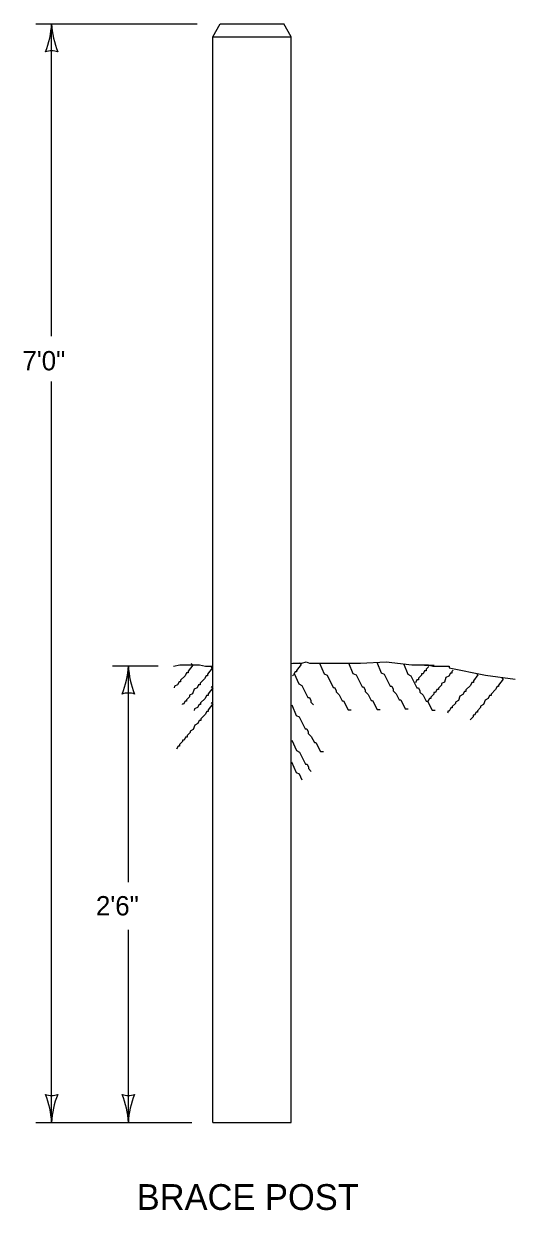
# Model space of a CAD drawing. Extents: x 49991 to 50288, y 49919 to 50011.
# Drawn here: x 50145.21 to 50148.35, y 49937.35 to 49944.96 of the extents above; entities that cross this region are included whole.
import ezdxf

# ---------------------------------------------------------------- set-up
doc = ezdxf.new("R2010")
doc.units = 0
for name, color, linetype in [('Level 1', 7, 'Continuous'), ('Level 2', 7, 'Continuous'), ('Level 5', 7, 'Continuous'), ('Level 7', 7, 'Continuous')]:
    doc.layers.add(name, color=color, linetype=linetype)

msp = doc.modelspace()

# ---------------------------------------------------------------- linework, layer by layer
at = {"layer": 'Level 1'}
for centre, radius, start, end in [((50144.8583, 49944.9773), 0.5262, 337.45601, 357.63952), ((50145.9349, 49944.9828), 0.5515, 182.82731, 202.07716), ((50145.3841, 49944.6521), 0.1296, 72.13882, 107.86118), ((50145.35, 49940.8626), 0.5262, 337.45601, 357.63952), ((50146.4265, 49940.8682), 0.5515, 182.82731, 202.07716), ((50145.8757, 49940.5375), 0.1296, 72.13882, 107.86118), ((50145.3841, 49938.2188), 0.1296, 252.13882, 287.86118), ((50144.8333, 49937.8882), 0.5515, 2.82731, 22.07716), ((50145.9099, 49937.8937), 0.5262, 157.45601, 177.63952), ((50145.8757, 49938.2188), 0.1296, 252.13882, 287.86118), ((50145.3249, 49937.8882), 0.5515, 2.82731, 22.07716), ((50146.4015, 49937.8937), 0.5262, 157.45601, 177.63952)]:
    msp.add_arc(centre, radius, start, end, dxfattribs=at)
at = {"layer": 'Level 5'}
msp.add_line((50147.7722, 49940.8452), (50147.833, 49940.8452), dxfattribs=at)
for points in [[(50146.1639, 49940.8401), (50146.2054, 49940.8483), (50146.3308, 49940.8483), (50146.3691, 49940.8387), (50146.417, 49940.8387)], [(50146.2777, 49940.8556), (50146.2874, 49940.8461), (50146.2586, 49940.8075), (50146.2586, 49940.7977), (50146.2488, 49940.7977), (50146.2393, 49940.7784), (50146.2102, 49940.7496), (50146.2102, 49940.74), (50146.2007, 49940.74), (50146.1909, 49940.7207), (50146.1718, 49940.711), (50146.1681, 49940.7002)], [(50146.4027, 49940.8362), (50146.4124, 49940.8266), (50146.3834, 49940.788), (50146.3834, 49940.7784), (50146.3738, 49940.7784), (50146.3641, 49940.7591), (50146.3352, 49940.7304), (50146.3352, 49940.7205), (50146.3255, 49940.7205), (50146.3159, 49940.7014), (50146.2968, 49940.6917), (50146.2869, 49940.6628), (50146.2677, 49940.6531), (50146.2677, 49940.6433), (50146.2484, 49940.624), (50146.2484, 49940.6146), (50146.2389, 49940.6146), (50146.229, 49940.5952), (50146.2195, 49940.5952), (50146.2195, 49940.593)], [(50146.9193, 49940.856), (50146.9283, 49940.858), (50146.9862, 49940.858), (50147.015, 49940.8675), (50147.0345, 49940.858), (50147.3331, 49940.858), (50147.3621, 49940.858), (50147.5262, 49940.8675), (50147.6898, 49940.8483), (50147.7959, 49940.8483), (50147.8246, 49940.8387), (50147.8922, 49940.8387), (50147.9306, 49940.8387), (50147.9306, 49940.829), (50148.1622, 49940.7808), (50148.3528, 49940.7563)], [(50146.9718, 49940.8604), (50146.9813, 49940.8506), (50146.9525, 49940.8122), (50146.9525, 49940.8026), (50146.9427, 49940.8026), (50146.9332, 49940.7833), (50146.9264, 49940.7765)], [(50147.0995, 49940.858), (50147.1283, 49940.7904), (50147.1476, 49940.7808), (50147.1861, 49940.7036), (50147.196, 49940.7036), (50147.2054, 49940.6843), (50147.2054, 49940.6748), (50147.2247, 49940.6555), (50147.244, 49940.6169), (50147.2537, 49940.6169), (50147.2826, 49940.5591), (50147.3019, 49940.5591)], [(50147.2849, 49940.8604), (50147.3138, 49940.7929), (50147.3332, 49940.7833), (50147.3717, 49940.7061), (50147.3814, 49940.7061), (50147.391, 49940.6868), (50147.391, 49940.6773), (50147.4103, 49940.658), (50147.4296, 49940.6194), (50147.4391, 49940.6194), (50147.4682, 49940.5616), (50147.4876, 49940.5616)], [(50147.4658, 49940.865), (50147.4946, 49940.7977), (50147.5139, 49940.788), (50147.5525, 49940.711), (50147.5621, 49940.711), (50147.5717, 49940.6917), (50147.5717, 49940.6822), (50147.5911, 49940.6627), (50147.6103, 49940.6241), (50147.6202, 49940.6241), (50147.6489, 49940.5664), (50147.6682, 49940.5664)], [(50147.6368, 49940.8556), (50147.6657, 49940.788), (50147.6851, 49940.7784), (50147.7236, 49940.7013), (50147.7331, 49940.7013), (50147.7429, 49940.6822), (50147.7429, 49940.6723), (50147.7623, 49940.653), (50147.7816, 49940.6145), (50147.791, 49940.6145), (50147.82, 49940.5566), (50147.8393, 49940.5566)], [(50147.7989, 49940.8368), (50147.7816, 49940.8193), (50147.7816, 49940.8097), (50147.7717, 49940.8097), (50147.7623, 49940.7906), (50147.7525, 49940.7906), (50147.7525, 49940.7808), (50147.733, 49940.7617), (50147.733, 49940.752), (50147.7236, 49940.752), (50147.714, 49940.7327)], [(50147.9556, 49940.813), (50147.9477, 49940.805), (50147.9477, 49940.7954), (50147.938, 49940.7954), (50147.9284, 49940.7763), (50147.9093, 49940.7664), (50147.8994, 49940.7375), (50147.8801, 49940.7279), (50147.8801, 49940.7182), (50147.8608, 49940.6989), (50147.8608, 49940.6893), (50147.8513, 49940.6893), (50147.8415, 49940.6702), (50147.832, 49940.6702), (50147.832, 49940.6605), (50147.8127, 49940.6412), (50147.8127, 49940.6316), (50147.8029, 49940.6316), (50147.7934, 49940.6121)], [(50146.9382, 49940.7927), (50146.967, 49940.7254), (50146.9862, 49940.7157), (50147.0248, 49940.6387), (50147.0345, 49940.6387), (50147.0441, 49940.6194), (50147.0441, 49940.6098), (50147.0619, 49940.592)], [(50148.1043, 49940.7929), (50148.114, 49940.7833), (50148.085, 49940.7447), (50148.085, 49940.7352), (50148.0754, 49940.7352), (50148.0657, 49940.7157), (50148.037, 49940.6868), (50148.037, 49940.6773), (50148.0271, 49940.6773), (50148.0176, 49940.658), (50147.9983, 49940.6482), (50147.9885, 49940.6195), (50147.9692, 49940.6098), (50147.9692, 49940.6002), (50147.9499, 49940.5809), (50147.9499, 49940.5714), (50147.9404, 49940.5714), (50147.9306, 49940.5521), (50147.9212, 49940.5521), (50147.9212, 49940.5423), (50147.9182, 49940.5393)], [(50148.2657, 49940.7664), (50148.2755, 49940.7566), (50148.2464, 49940.7182), (50148.2464, 49940.7086), (50148.2369, 49940.7086), (50148.2271, 49940.6893), (50148.1983, 49940.6605), (50148.1983, 49940.6507), (50148.1887, 49940.6507), (50148.179, 49940.6316), (50148.1597, 49940.622), (50148.1499, 49940.5928), (50148.1308, 49940.5833), (50148.1308, 49940.5737), (50148.1117, 49940.5541), (50148.1117, 49940.5447), (50148.1019, 49940.5447), (50148.0922, 49940.5254), (50148.0826, 49940.5254), (50148.0826, 49940.5157), (50148.0632, 49940.4964)], [(50146.4059, 49940.7101), (50146.4156, 49940.7006), (50146.3868, 49940.6619), (50146.3868, 49940.6521), (50146.377, 49940.6521), (50146.3675, 49940.6328), (50146.3384, 49940.604), (50146.3384, 49940.5944), (50146.3289, 49940.5944), (50146.3191, 49940.5751), (50146.3, 49940.5655), (50146.2964, 49940.5546)], [(50146.4063, 49940.6069), (50146.4159, 49940.5974), (50146.3869, 49940.5588), (50146.3869, 49940.549), (50146.3775, 49940.549), (50146.3677, 49940.5299), (50146.3389, 49940.501), (50146.3389, 49940.4913), (50146.3293, 49940.4913), (50146.3196, 49940.472), (50146.3003, 49940.4624), (50146.2905, 49940.4334), (50146.2712, 49940.4238), (50146.2712, 49940.4141), (50146.2519, 49940.3948), (50146.2519, 49940.3852), (50146.2424, 49940.3852), (50146.2329, 49940.3659), (50146.223, 49940.3659), (50146.223, 49940.3562), (50146.2037, 49940.337), (50146.2037, 49940.3272), (50146.1941, 49940.3272), (50146.1844, 49940.3081)], [(50146.9219, 49940.5916), (50146.9507, 49940.5241), (50146.97, 49940.5145), (50147.0085, 49940.4372), (50147.0184, 49940.4372), (50147.0278, 49940.4179), (50147.0278, 49940.4084), (50147.0471, 49940.3891), (50147.0665, 49940.3505), (50147.0762, 49940.3505), (50147.1051, 49940.2927), (50147.1244, 49940.2927)], [(50146.9234, 49940.366), (50146.9522, 49940.2987), (50146.9714, 49940.289), (50147.01, 49940.212), (50147.0197, 49940.212), (50147.0293, 49940.1927), (50147.0293, 49940.1831), (50147.0471, 49940.1653)], [(50146.9206, 49940.2257), (50146.9496, 49940.1582), (50146.9689, 49940.1487), (50146.9874, 49940.1114)]]:
    msp.add_lwpolyline(points, dxfattribs=at)
at = {"layer": 'Level 7'}
for p, q in [((50145.2835, 49944.9556), (50146.3171, 49944.9556)), ((50145.3841, 49942.9534), (50145.3841, 49944.9556)), ((50146.4158, 49944.8721), (50146.464, 49944.9556)), ((50146.464, 49944.9556), (50146.8705, 49944.9556)), ((50146.9187, 49944.8721), (50146.8705, 49944.9556)), ((50146.4158, 49944.8721), (50146.9187, 49944.8721)), ((50146.4158, 49937.9154), (50146.4158, 49944.8721)), ((50146.9187, 49943.6984), (50146.9187, 49944.8721)), ((50146.9187, 49937.9154), (50146.9187, 49943.6984)), ((50145.3841, 49937.9154), (50145.3841, 49942.6623)), ((50145.7751, 49940.8409), (50146.0655, 49940.8409)), ((50145.8757, 49939.456), (50145.8757, 49940.8409)), ((50145.8757, 49937.9154), (50145.8757, 49939.1501)), ((50145.2835, 49937.9154), (50146.2827, 49937.9154)), ((50146.4158, 49937.9154), (50146.9187, 49937.9154))]:
    msp.add_line(p, q, dxfattribs=at)

# ---------------------------------------------------------------- texts
at = {"layer": 'Level 2'}
for s, p in [('7\'0"', (50145.1974, 49942.7347)), ('2\'6"', (50145.6682, 49939.2425))]:
    msp.add_text(s, height=0.12374, rotation=360, dxfattribs=at).set_placement(p)
msp.add_text('BRACE POST', height=0.16498, dxfattribs=at).set_placement((50145.9291, 49937.3556))

doc.saveas('drawing.dxf')
